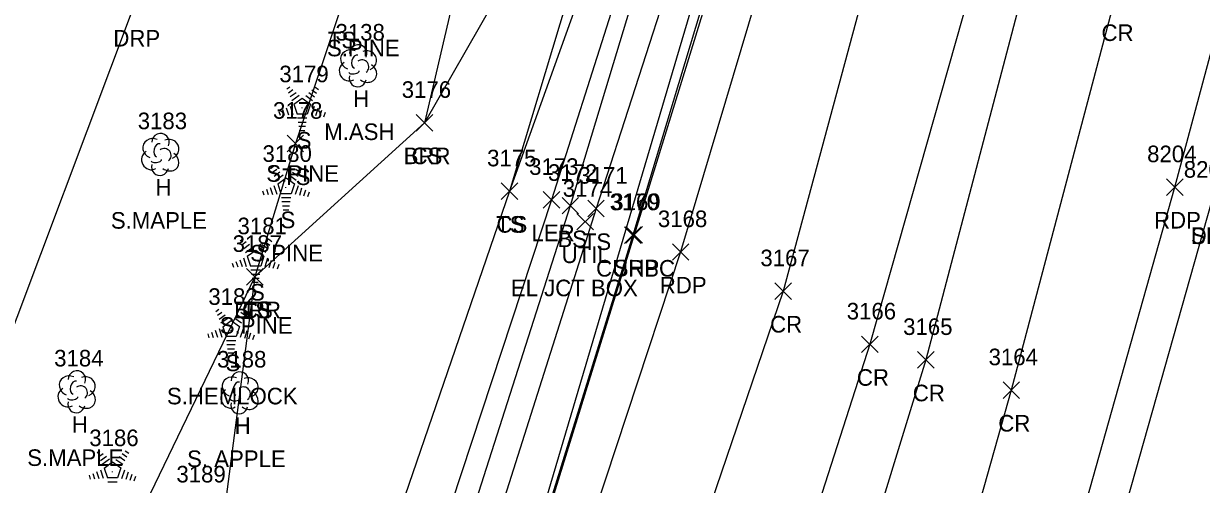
# Model space of a CAD drawing. Extents: x 1462089 to 1464015, y 730534 to 736144.
# Drawn here: x 1462997.1 to 1463139, y 733027.8 to 733083.4 of the extents above; entities that cross this region are included whole.
import ezdxf

# ---------------------------------------------------------------- set-up
doc = ezdxf.new("R2010")
doc.units = 0
for name, color, linetype in [('DCP', 7, 'Continuous'), ('L_A', 7, 'Continuous'), ('L_C', 7, 'Continuous'), ('L_I', 7, 'Continuous'), ('L_TIC', 7, 'Continuous'), ('LABL', 7, 'Continuous'), ('LARO', 7, 'Continuous'), ('LELB', 7, 'Continuous'), ('LTC', 7, 'Continuous'), ('LTD', 7, 'Continuous'), ('P_A', 7, 'Continuous'), ('P_I', 7, 'Continuous'), ('P_TIC', 7, 'Continuous'), ('PET', 7, 'Continuous'), ('PRC', 7, 'Continuous'), ('PSP', 7, 'Continuous'), ('R_A', 7, 'Continuous'), ('R_I', 7, 'Continuous'), ('R_TIC', 7, 'Continuous'), ('RC', 7, 'Continuous'), ('RDP', 7, 'Continuous'), ('U_A', 7, 'Continuous'), ('U_C', 7, 'Continuous'), ('U_I', 7, 'Continuous'), ('UDEFAULT', 7, 'Continuous')]:
    doc.layers.add(name, color=color, linetype=linetype)

msp = doc.modelspace()

# ---------------------------------------------------------------- linework, layer by layer
at = {"layer": 'DCP'}
msp.add_lwpolyline([(1463113.91, 733208.21), (1463020.77, 732893.28)], dxfattribs=at)
at = {"layer": 'L_TIC'}
for points in [[(1463044.39, 733070.47), (1463046.39, 733072.47)], [(1463046.39, 733070.47), (1463044.39, 733072.47)], [(1463044.39, 733070.47), (1463046.39, 733072.47)], [(1463046.39, 733070.47), (1463044.39, 733072.47)], [(1463028.83, 733067.95), (1463030.83, 733069.95)], [(1463030.83, 733067.95), (1463028.83, 733069.95)], [(1463054.63, 733062.21), (1463056.63, 733064.21)], [(1463056.63, 733062.21), (1463054.63, 733064.21)], [(1463054.63, 733062.21), (1463056.63, 733064.21)], [(1463056.63, 733062.21), (1463054.63, 733064.21)], [(1463059.71, 733061.18), (1463061.71, 733063.18)], [(1463061.71, 733061.18), (1463059.71, 733063.18)], [(1463061.97, 733060.46), (1463063.97, 733062.46)], [(1463063.97, 733060.46), (1463061.97, 733062.46)], [(1463065.07, 733060.12), (1463067.07, 733062.12)], [(1463067.07, 733060.12), (1463065.07, 733062.12)], [(1463023.96, 733051.89), (1463025.96, 733053.89)], [(1463025.96, 733051.89), (1463023.96, 733053.89)], [(1463023.96, 733051.89), (1463025.96, 733053.89)], [(1463025.96, 733051.89), (1463023.96, 733053.89)], [(1463023.96, 733051.89), (1463025.96, 733053.89)], [(1463025.96, 733051.89), (1463023.96, 733053.89)]]:
    msp.add_lwpolyline(points, dxfattribs=at)
at = {"layer": 'LABL'}
msp.add_lwpolyline([(1463052.45, 733194.5), (1463067.07, 733192.93), (1463078.58, 733189.91), (1463086.91, 733186.3), (1463094.26, 733183.58), (1463092.11, 733172.76), (1463083.33, 733140.42), (1463080.34, 733131.51), (1463076.28, 733126.39), (1463067.39, 733109.86), (1463045.39, 733071.47), (1463024.96, 733052.89)], dxfattribs=at)
at = {"layer": 'LARO'}
msp.add_lwpolyline([(1463094.76, 733228.15), (1463096.03, 733229.51), (1463107.11, 733225.67), (1463106.44, 733220.79), (1463101.84, 733210.57), (1463094.26, 733183.58), (1463093.23, 733172.66), (1463084.96, 733140.71), (1463082.5, 733130.85), (1463075.1, 733107.4), (1463060.71, 733062.18), (1463041.43, 733003.63), (1463027.29, 732956.25), (1463020.7, 732939.68), (1463009.72, 732922.59), (1463000.8, 732913.83)], dxfattribs=at)
at = {"layer": 'LELB'}
for points in [[(1463067.07, 733192.93), (1463070.43, 733198.24), (1463078.66, 733227.75), (1463094.76, 733228.15), (1463099.99, 733222.4), (1463095.74, 733212.27), (1463086.91, 733186.3), (1463084.26, 733175.21), (1463078.19, 733140.32), (1463061.26, 733133.55), (1463056.17, 733129.91), (1463054.78, 733128.23), (1463056, 733122.82), (1463058.28, 733122.51), (1463065.52, 733123.03), (1463076.28, 733126.39), (1463069.53, 733109.4), (1463055.63, 733063.21), (1463034.63, 733001.95)], [(1463108.71, 733226.1), (1463108.78, 733215.45), (1463107.91, 733210.67), (1463106.52, 733207.37), (1463097.65, 733182.34), (1463096.33, 733171.82), (1463062.97, 733061.46), (1463044.31, 733003.12), (1463029.33, 732955.28), (1463018.11, 732921.02), (1463012.52, 732895.45), (1463002.14, 732868.56), (1462989.94, 732828.37), (1462974.14, 732778.17), (1462962.05, 732738.86), (1462942.09, 732684.7)], [(1463108.71, 733226.1), (1463110.44, 733215.45), (1463109.61, 733208.14), (1463106.26, 733200.46), (1463099.08, 733171.5), (1463080.2, 733104.81), (1463066.07, 733061.12), (1463047.44, 733002.3), (1463031.89, 732954.26), (1463021.29, 732920.45), (1463016.04, 732893.81), (1463006.16, 732867.27), (1462993.39, 732826.96), (1462975.9, 732776.47), (1462964.59, 732738.3), (1462945.3, 732683.44)], [(1463084.96, 733140.71), (1463083.33, 733140.42), (1463075.18, 733134.32), (1463064.14, 733130.76), (1463056.73, 733129.29), (1463058.13, 733125.1), (1463066.3, 733126.91), (1463074.64, 733128.86), (1463080.34, 733131.51), (1463082.5, 733130.85), (1463071.67, 733107.97), (1463055.63, 733063.21)], [(1463058.13, 733125.1), (1463058.28, 733122.51), (1463056.05, 733119.51), (1463052.64, 733102.51), (1463045.39, 733071.47)], [(1463035.34, 733085.44), (1463029.83, 733068.95), (1463024.96, 733052.89), (1463005.74, 733013.02), (1462985.96, 732964.97), (1462972.93, 732929.05)], [(1463024.96, 733052.89), (1463019.37, 733009.96), (1463000.01, 732962.33), (1462984.86, 732926.01), (1462972.76, 732908.94), (1462960.37, 732884.47), (1462958.09, 732841.86), (1462948.33, 732829.18), (1462951.8, 732798.65), (1462940.09, 732777.68), (1462936.2, 732747.89), (1462927.88, 732723.49), (1462921.5, 732707.29), (1462904.86, 732665.94), (1462895.56, 732628.88), (1462895.22, 732616.02)]]:
    msp.add_lwpolyline(points, dxfattribs=at)
at = {"layer": 'LTC'}
for p, q in [((1463028.8, 733075.55), (1463029.15, 733075.81)), ((1463029.01, 733075.09), (1463029.53, 733075.47)), ((1463029.21, 733074.62), (1463029.92, 733075.13)), ((1463029.42, 733074.16), (1463030.3, 733074.79)), ((1463031.08, 733074.75), (1463031.89, 733074.16)), ((1463031.45, 733075.1), (1463032.13, 733074.6)), ((1463031.82, 733075.45), (1463032.37, 733075.05)), ((1463032.19, 733075.79), (1463032.61, 733075.49)), ((1463028.28, 733073.05), (1463028.5, 733072.4)), ((1463028.74, 733073.27), (1463029.01, 733072.43)), ((1463029.19, 733073.48), (1463029.53, 733072.46)), ((1463029.65, 733073.7), (1463030.66, 733074.44)), ((1463029.65, 733073.7), (1463030.04, 733072.51)), ((1463030.66, 733074.44), (1463031.66, 733073.71)), ((1463031.66, 733073.71), (1463031.27, 733072.51)), ((1463032.1, 733073.44), (1463031.76, 733072.4)), ((1463032.54, 733073.19), (1463032.25, 733072.31)), ((1463027.83, 733072.83), (1463027.98, 733072.37)), ((1463031.27, 733072.51), (1463030.04, 733072.51)), ((1463031.23, 733072.01), (1463030.08, 733072.01)), ((1463032.98, 733072.94), (1463032.75, 733072.21)), ((1463033.43, 733072.69), (1463033.24, 733072.12)), ((1463031.14, 733071.51), (1463030.16, 733071.51)), ((1463031.06, 733071.01), (1463030.23, 733071.01)), ((1463030.98, 733070.51), (1463030.3, 733070.51)), ((1463026.85, 733065.96), (1463027.2, 733066.21)), ((1463030.25, 733066.2), (1463030.67, 733065.89)), ((1463027.06, 733065.49), (1463027.59, 733065.88)), ((1463027.27, 733065.03), (1463027.97, 733065.54)), ((1463027.48, 733064.56), (1463028.36, 733065.2)), ((1463027.7, 733064.11), (1463028.71, 733064.84)), ((1463028.71, 733064.84), (1463029.71, 733064.11)), ((1463029.13, 733065.15), (1463029.94, 733064.56)), ((1463029.5, 733065.5), (1463030.18, 733065.01)), ((1463029.88, 733065.85), (1463030.43, 733065.45)), ((1463025.88, 733063.24), (1463026.03, 733062.77)), ((1463026.34, 733063.45), (1463026.55, 733062.8)), ((1463026.79, 733063.67), (1463027.06, 733062.83)), ((1463027.25, 733063.89), (1463027.58, 733062.87)), ((1463027.7, 733064.11), (1463028.09, 733062.91)), ((1463029.71, 733064.11), (1463029.32, 733062.91)), ((1463030.15, 733063.84), (1463029.81, 733062.8)), ((1463030.59, 733063.59), (1463030.31, 733062.71)), ((1463031.04, 733063.34), (1463030.8, 733062.61)), ((1463031.48, 733063.09), (1463031.29, 733062.52)), ((1463029.32, 733062.91), (1463028.09, 733062.91)), ((1463029.28, 733062.41), (1463028.14, 733062.41)), ((1463029.2, 733061.91), (1463028.21, 733061.91)), ((1463029.11, 733061.41), (1463028.28, 733061.41)), ((1463029.03, 733060.91), (1463028.35, 733060.91)), ((1463023.18, 733057.23), (1463023.54, 733057.49)), ((1463026.58, 733057.47), (1463027, 733057.16)), ((1463023.39, 733056.76), (1463023.92, 733057.15)), ((1463023.6, 733056.3), (1463024.31, 733056.81)), ((1463023.81, 733055.83), (1463024.69, 733056.47)), ((1463024.04, 733055.38), (1463025.05, 733056.11)), ((1463025.05, 733056.11), (1463026.04, 733055.39)), ((1463025.47, 733056.42), (1463026.28, 733055.84)), ((1463025.84, 733056.77), (1463026.52, 733056.28)), ((1463026.21, 733057.12), (1463026.76, 733056.72)), ((1463022.67, 733054.72), (1463022.88, 733054.07)), ((1463023.13, 733054.94), (1463023.4, 733054.11)), ((1463023.58, 733055.16), (1463023.91, 733054.14)), ((1463024.04, 733055.38), (1463024.42, 733054.18)), ((1463026.04, 733055.39), (1463025.65, 733054.18)), ((1463026.48, 733055.12), (1463026.14, 733054.08)), ((1463026.93, 733054.86), (1463026.64, 733053.98)), ((1463027.37, 733054.61), (1463027.13, 733053.89)), ((1463022.22, 733054.51), (1463022.37, 733054.04)), ((1463025.65, 733054.18), (1463024.42, 733054.18)), ((1463025.62, 733053.68), (1463024.47, 733053.68)), ((1463025.53, 733053.18), (1463024.54, 733053.18)), ((1463027.82, 733054.36), (1463027.63, 733053.79)), ((1463025.45, 733052.68), (1463024.62, 733052.68)), ((1463025.36, 733052.18), (1463024.69, 733052.18)), ((1463020.23, 733048.71), (1463020.59, 733048.97)), ((1463023.63, 733048.95), (1463024.05, 733048.65)), ((1463020.44, 733048.25), (1463020.97, 733048.63)), ((1463020.65, 733047.78), (1463021.35, 733048.29)), ((1463020.86, 733047.32), (1463021.74, 733047.95)), ((1463021.08, 733046.86), (1463022.1, 733047.6)), ((1463022.1, 733047.6), (1463023.09, 733046.87)), ((1463022.52, 733047.91), (1463023.33, 733047.32)), ((1463022.89, 733048.26), (1463023.57, 733047.76)), ((1463023.26, 733048.61), (1463023.81, 733048.21)), ((1463019.72, 733046.21), (1463019.93, 733045.56)), ((1463020.17, 733046.43), (1463020.45, 733045.59)), ((1463020.63, 733046.64), (1463020.96, 733045.62)), ((1463021.08, 733046.86), (1463021.47, 733045.67)), ((1463023.09, 733046.87), (1463022.7, 733045.67)), ((1463023.53, 733046.6), (1463023.19, 733045.56)), ((1463023.97, 733046.35), (1463023.69, 733045.46)), ((1463024.42, 733046.1), (1463024.18, 733045.37)), ((1463019.26, 733045.99), (1463019.42, 733045.52)), ((1463022.7, 733045.67), (1463021.47, 733045.67)), ((1463022.66, 733045.17), (1463021.52, 733045.17)), ((1463022.58, 733044.67), (1463021.59, 733044.67)), ((1463024.86, 733045.85), (1463024.68, 733045.27)), ((1463022.5, 733044.17), (1463021.66, 733044.17)), ((1463022.41, 733043.67), (1463021.74, 733043.67)), ((1463005.93, 733031.67), (1463006.28, 733031.93)), ((1463009.33, 733031.91), (1463009.75, 733031.6)), ((1463006.14, 733031.2), (1463006.67, 733031.59)), ((1463006.35, 733030.74), (1463007.05, 733031.25)), ((1463006.56, 733030.27), (1463007.44, 733030.91)), ((1463006.78, 733029.82), (1463007.79, 733030.55)), ((1463007.79, 733030.55), (1463008.79, 733029.83)), ((1463008.21, 733030.86), (1463009.02, 733030.28)), ((1463008.58, 733031.21), (1463009.26, 733030.72)), ((1463008.96, 733031.56), (1463009.51, 733031.16)), ((1463005.42, 733029.16), (1463005.63, 733028.51)), ((1463005.87, 733029.38), (1463006.14, 733028.55)), ((1463006.33, 733029.6), (1463006.66, 733028.58)), ((1463006.78, 733029.82), (1463007.17, 733028.62)), ((1463008.79, 733029.83), (1463008.4, 733028.62)), ((1463009.23, 733029.56), (1463008.89, 733028.52)), ((1463009.67, 733029.3), (1463009.39, 733028.42)), ((1463010.12, 733029.05), (1463009.88, 733028.33)), ((1463004.96, 733028.95), (1463005.11, 733028.48)), ((1463008.4, 733028.62), (1463007.17, 733028.62)), ((1463008.36, 733028.12), (1463007.22, 733028.12)), ((1463010.56, 733028.8), (1463010.37, 733028.23))]:
    msp.add_line(p, q, dxfattribs=at)
at = {"layer": 'LTD'}
for p, q in [((1463037.36, 733078.38), (1463037.36, 733078.38)), ((1463037.36, 733078.38), (1463037.36, 733078.38)), ((1463013.52, 733067.69), (1463013.52, 733067.69)), ((1463013.52, 733067.69), (1463013.52, 733067.69)), ((1463003.45, 733039.07), (1463003.45, 733039.07)), ((1463003.45, 733039.07), (1463003.45, 733039.07)), ((1463023.08, 733038.94), (1463023.08, 733038.94)), ((1463023.08, 733038.94), (1463023.08, 733038.94))]:
    msp.add_line(p, q, dxfattribs=at)
for centre in [(1463037.41, 733079.82), (1463013.57, 733069.13), (1463003.5, 733040.5), (1463023.13, 733040.37)]:
    msp.add_arc(centre, 1.05, 335.5272, 180.9563, dxfattribs=at)
for centre, major_axis, ratio, start_param, end_param in [((1463036.57, 733079.05), (1.21, -0.51), 0.895232, 1.570796, 4.712389), ((1463038.4, 733078.97), (-1.14, -0.48), 0.949671, 1.570796, 4.712389), ((1463036.28, 733077.68), (0.58, -1.04), 0.959034, 3.141593, 6.283185), ((1463037.15, 733078.84), (-0.208, -0.792), 0.645439, 3.141593, 6.283185), ((1463037.86, 733078.22), (-0.5, 0.667), 0.989748, 3.141593, 6.283185), ((1463036.9, 733077.63), (-0.625, -0.083), 0.423636, 0, 3.141593), ((1463038.36, 733077.55), (-1.09, 0.79), 0.841452, 1.570796, 4.712389), ((1463037.36, 733076.88), (0.26, 1.06), 0.942809, 1.570796, 4.712389), ((1463012.73, 733068.36), (1.21, -0.51), 0.895232, 1.570796, 4.712389), ((1463013.32, 733068.15), (-0.208, -0.792), 0.645439, 3.141593, 6.283185), ((1463014.57, 733068.28), (-1.14, -0.48), 0.949671, 1.570796, 4.712389), ((1463012.44, 733066.98), (0.58, -1.04), 0.959034, 3.141593, 6.283185), ((1463014.02, 733067.53), (-0.5, 0.667), 0.989748, 3.141593, 6.283185), ((1463014.52, 733066.86), (-1.09, 0.79), 0.841452, 1.570796, 4.712389), ((1463013.52, 733066.19), (0.26, 1.06), 0.942809, 1.570796, 4.712389), ((1463013.07, 733066.94), (-0.625, -0.083), 0.423636, 0, 3.141593), ((1463002.66, 733039.73), (1.21, -0.51), 0.895232, 1.570796, 4.712389), ((1463003.24, 733039.52), (-0.208, -0.792), 0.645439, 3.141593, 6.283185), ((1463004.49, 733039.65), (-1.14, -0.48), 0.949671, 1.570796, 4.712389), ((1463022.29, 733039.6), (1.21, -0.51), 0.895232, 1.570796, 4.712389), ((1463024.12, 733039.52), (-1.14, -0.48), 0.949671, 1.570796, 4.712389), ((1463002.37, 733038.36), (0.58, -1.04), 0.959034, 3.141593, 6.283185), ((1463003.95, 733038.9), (-0.5, 0.667), 0.989748, 3.141593, 6.283185), ((1463004.45, 733038.23), (-1.09, 0.79), 0.841452, 1.570796, 4.712389), ((1463022, 733038.23), (0.58, -1.04), 0.959034, 3.141593, 6.283185), ((1463022.87, 733039.4), (-0.208, -0.792), 0.645439, 3.141593, 6.283185), ((1463023.58, 733038.77), (-0.5, 0.667), 0.989748, 3.141593, 6.283185), ((1463024.08, 733038.1), (-1.09, 0.79), 0.841452, 1.570796, 4.712389), ((1463003.45, 733037.57), (0.26, 1.06), 0.942809, 1.570796, 4.712389), ((1463002.99, 733038.32), (-0.625, -0.083), 0.423636, 0, 3.141593), ((1463023.08, 733037.44), (0.26, 1.06), 0.942809, 1.570796, 4.712389), ((1463022.62, 733038.19), (-0.625, -0.083), 0.423636, 0, 3.141593)]:
    msp.add_ellipse(centre, major_axis=major_axis, ratio=ratio, start_param=start_param, end_param=end_param, dxfattribs=at)
at = {"layer": 'P_TIC'}
for points in [[(1463134.84, 733062.71), (1463136.84, 733064.71)], [(1463136.84, 733062.71), (1463134.84, 733064.71)], [(1463069.66, 733056.94), (1463071.66, 733058.94)], [(1463071.66, 733056.94), (1463069.66, 733058.94)], [(1463075.27, 733054.88), (1463077.27, 733056.88)], [(1463077.27, 733054.88), (1463075.27, 733056.88)], [(1463087.62, 733050.16), (1463089.62, 733052.16)], [(1463089.62, 733050.16), (1463087.62, 733052.16)], [(1463098.08, 733043.74), (1463100.08, 733045.74)], [(1463100.08, 733043.74), (1463098.08, 733045.74)], [(1463104.83, 733041.87), (1463106.83, 733043.87)], [(1463106.83, 733041.87), (1463104.83, 733043.87)], [(1463115.13, 733038.22), (1463117.13, 733040.22)], [(1463117.13, 733038.22), (1463115.13, 733040.22)]]:
    msp.add_lwpolyline(points, dxfattribs=at)
at = {"layer": 'PET'}
for points in [[(1463023.48, 732671), (1463036.19, 732713.31), (1463039.97, 732724.95), (1463046.42, 732748.22), (1463045.94, 732761.16), (1463059.87, 732803.81), (1463070.46, 732836.88), (1463084.18, 732884.08), (1463100.27, 732939.23), (1463111.27, 732977.09), (1463121.46, 733012.56), (1463135.84, 733063.71), (1463147.86, 733108.52), (1463159.44, 733157.54), (1463168.48, 733199.6), (1463175.72, 733236.25), (1463184.37, 733283.25), (1463191.27, 733323.49), (1463191.08, 733323.84), (1463204.04, 733400.9), (1463213.28, 733462.86)], [(1463162.64, 733438.25), (1463155.29, 733389.19), (1463147.91, 733342.63), (1463141.51, 733306.47), (1463132.06, 733260.3), (1463123.36, 733223.56), (1463108.71, 733168.54), (1463089.87, 733101.56), (1463076.27, 733055.88), (1463056.85, 732997.04), (1463043.72, 732952), (1463030.35, 732910.94), (1463015.8, 732864.49), (1463002.53, 732823.32), (1462986.53, 732773.32), (1462974.36, 732735), (1462957.21, 732680.82)]]:
    msp.add_lwpolyline(points, dxfattribs=at)
at = {"layer": 'PRC'}
for points in [[(1463173.05, 733431.97), (1463166.54, 733387.93), (1463158.95, 733340.73), (1463152.26, 733304.55), (1463143.59, 733257.28), (1463135.29, 733220.7), (1463120.9, 733164.91), (1463101.36, 733098.43), (1463088.62, 733051.16), (1463070, 732996.41), (1463055.29, 732948.06), (1463043.07, 732909.01), (1463027.36, 732860.42), (1463013.91, 732819.27), (1462999.18, 732769.26), (1462985.72, 732731.93), (1462969.44, 732677.27)], [(1463184.26, 733428.99), (1463177.5, 733386.21), (1463169.42, 733335), (1463162.87, 733301.13), (1463154.54, 733254.52), (1463145.29, 733216.48), (1463131.67, 733162.65), (1463112.82, 733093.24), (1463099.08, 733044.74), (1463082.5, 732993.09), (1463066.93, 732944.79), (1463054.22, 732905.14), (1463038.5, 732856.13), (1463025.08, 732814.55), (1463009.9, 732766.25), (1462997.49, 732727.73), (1462980.34, 732670.55), (1462968.82, 732637.25), (1462956.14, 732592.49), (1462943.23, 732555.63), (1462933.85, 732526.13), (1462921.41, 732485.16), (1462905.69, 732440.94), (1462895.98, 732404.53)], [(1463173.56, 733299.02), (1463165.51, 733252.57), (1463157.36, 733210.85), (1463147.48, 733159.84), (1463128.56, 733086.33), (1463116.13, 733039.22), (1463100.45, 732983.58), (1463087.95, 732938.84), (1463073.8, 732896.76), (1463059.6, 732849.78), (1463047.56, 732806.21), (1463032.36, 732758.17), (1463016.83, 732714.7), (1463001.87, 732663.36), (1462991.08, 732629.32), (1462977.35, 732584.7), (1462966.06, 732548.54), (1462956.48, 732518.6), (1462941.54, 732474.04), (1462928.1, 732429.75), (1462916.12, 732396.98)], [(1463154.54, 733254.52), (1463146.61, 733215.85), (1463135.44, 733161.47), (1463118.39, 733090.76), (1463105.83, 733042.87), (1463089.37, 732989.24), (1463076.43, 732943.44), (1463063.88, 732901.54), (1463049.78, 732852.76), (1463036.58, 732810.58), (1463021.66, 732763.56), (1463007.35, 732718.7), (1462991.11, 732667.44), (1462980.42, 732633.72), (1462966.43, 732588.15), (1462955.05, 732551.99), (1462945.51, 732521.94), (1462931.54, 732478.17), (1462917.14, 732435.42), (1462906.01, 732400.46)]]:
    msp.add_lwpolyline(points, dxfattribs=at)
at = {"layer": 'PSP'}
for points in [[(1463046.42, 732748.22), (1463053.17, 732770.64), (1463063.86, 732801.92), (1463074.6, 732835.37), (1463088.19, 732883.02), (1463104.54, 732937.8), (1463115.69, 732976.25), (1463126.02, 733011.46), (1463140.26, 733061.84), (1463152.14, 733107.42), (1463163.97, 733156.32), (1463173.72, 733198.02), (1463181.46, 733234.06), (1463190.45, 733280.83), (1463197.61, 733321.61), (1463206.08, 733372.72), (1463210.25, 733399.69), (1463219.8, 733463.02)], [(1463155.47, 733437.1), (1463151.69, 733409.08), (1463149, 733391.93), (1463141.96, 733349.08), (1463135.18, 733308.49), (1463125.93, 733264.09), (1463122.72, 733251.49), (1463119.11, 733234.45), (1463113.24, 733211.25), (1463103.08, 733170.52), (1463084.78, 733103.69), (1463070.66, 733057.94), (1463052.86, 733000.45), (1463038.28, 732952.98), (1463025.31, 732912.14), (1463010.74, 732866.35), (1462997.43, 732825.46), (1462981.2, 732774.91), (1462968.73, 732736.5), (1462951.61, 732681.88)]]:
    msp.add_lwpolyline(points, dxfattribs=at)
at = {"layer": 'R_TIC'}
for points in [[(1463069.5, 733056.91), (1463071.5, 733058.91)], [(1463071.5, 733056.91), (1463069.5, 733058.91)]]:
    msp.add_lwpolyline(points, dxfattribs=at)
at = {"layer": 'RC'}
msp.add_lwpolyline([(1463111.2, 733221.62), (1463111.65, 733221.54), (1463112.56, 733218.83), (1463113.16, 733213.96), (1463112.93, 733211.4), (1463102.86, 733170.54), (1463084.32, 733103.79), (1463070.5, 733057.91), (1463052.69, 733000.48), (1463038.08, 732953.17), (1463025.2, 732912.25), (1463010.5, 732866.43), (1462997.21, 732825.5), (1462981.06, 732775.17), (1462968.5, 732736.53), (1462951.35, 732681.84)], dxfattribs=at)
at = {"layer": 'RDP'}
msp.add_lwpolyline([(1463003.46, 733112.43), (1463010.21, 733105.22), (1463012.77, 733098.29), (1463010.4, 733085.66), (1462993.36, 733040.36), (1462985.36, 733018.62), (1462967.62, 732969.66)], dxfattribs=at)
at = {"layer": 'UDEFAULT'}
for points in [[(1463063.76, 733058.54), (1463065.76, 733060.54)], [(1463065.76, 733058.54), (1463063.76, 733060.54)]]:
    msp.add_lwpolyline(points, dxfattribs=at)

# ---------------------------------------------------------------- texts
at = {"layer": 'L_A'}
for s, p in [('TS', (1463033.75, 733080.44)), ('H', (1463036.79, 733073.38)), ('S', (1463029.99, 733068.35)), ('BRR', (1463042.88, 733066.47)), ('CS', (1463043.83, 733066.47)), ('TS', (1463028.24, 733063.95)), ('H', (1463012.96, 733062.69)), ('S', (1463028.04, 733058.75)), ('TS', (1463054.04, 733058.21)), ('CS', (1463054.07, 733058.21)), ('LER', (1463058.29, 733057.18)), ('BS', (1463061.41, 733056.46)), ('TS', (1463064.48, 733056.12)), ('S', (1463024.37, 733050.02)), ('BRR', (1463022.45, 733047.89)), ('TS', (1463023.37, 733047.89)), ('CS', (1463023.4, 733047.89)), ('S', (1463021.42, 733041.5)), ('H', (1463002.88, 733034.07)), ('H', (1463022.51, 733033.94))]:
    msp.add_text(s, height=2, dxfattribs=at).set_placement(p)
at = {"layer": 'L_C'}
for s, p in [('S.PINE', (1463033.64, 733079.48)), ('M.ASH', (1463033.31, 733069.38)), ('S.PINE', (1463026.33, 733064.35)), ('S.MAPLE', (1463007.59, 733058.69)), ('S.PINE', (1463024.39, 733054.75)), ('S.PINE', (1463020.72, 733046.02)), ('S.HEMLOCK', (1463014.35, 733037.5)), ('S.MAPLE', (1462997.51, 733030.07)), ('S. APPLE', (1463016.78, 733029.94))]:
    msp.add_text(s, height=2, dxfattribs=at).set_placement(p)
at = {"layer": 'L_I'}
for s, p in [('3138', (1463034.67, 733081.38)), ('3179', (1463027.9, 733076.35)), ('3176', (1463042.65, 733074.47)), ('3176', (1463042.65, 733074.47)), ('3178', (1463027.14, 733071.95)), ('3183', (1463010.83, 733070.69)), ('3180', (1463025.87, 733066.75)), ('3175', (1463052.94, 733066.21)), ('3175', (1463052.94, 733066.21)), ('3173', (1463058.01, 733065.18)), ('3172', (1463060.28, 733064.46)), ('3171', (1463063.94, 733064.12)), ('3181', (1463022.86, 733058.02)), ('3187', (1463022.27, 733055.89)), ('3187', (1463022.27, 733055.89)), ('3187', (1463022.27, 733055.89)), ('3182', (1463019.34, 733049.5)), ('3184', (1463000.76, 733042.07)), ('3188', (1463020.39, 733041.94)), ('3186', (1463004.99, 733032.46)), ('3189', (1463015.49, 733028.08))]:
    msp.add_text(s, height=2, dxfattribs=at).set_placement(p)
at = {"layer": 'LTC'}
for p in [(1463030.54, 733073.45), (1463028.6, 733063.85), (1463024.93, 733055.12), (1463021.98, 733046.61), (1463007.68, 733029.56)]:
    msp.add_text('.', height=1.04, rotation=270, dxfattribs=at).set_placement(p)
at = {"layer": 'P_A'}
for s, p in [('CR', (1463127, 733081.33)), ('RDP', (1463133.33, 733058.71)), ('SHP', (1463137.79, 733056.84)), ('SHP', (1463068.2, 733052.94)), ('RDP', (1463073.76, 733050.88)), ('CR', (1463087.05, 733046.16)), ('CR', (1463097.52, 733039.74)), ('CR', (1463104.26, 733037.87)), ('CR', (1463114.56, 733034.22))]:
    msp.add_text(s, height=2, dxfattribs=at).set_placement(p)
at = {"layer": 'P_I'}
for s, p in [('8204', (1463132.5, 733066.71)), ('8203', (1463136.92, 733064.84)), ('3169', (1463067.91, 733060.94)), ('3168', (1463073.53, 733058.88)), ('3167', (1463085.88, 733054.16)), ('3166', (1463096.29, 733047.74)), ('3165', (1463103.09, 733045.87)), ('3164', (1463113.39, 733042.22))]:
    msp.add_text(s, height=2, dxfattribs=at).set_placement(p)
at = {"layer": 'R_A'}
for s, p in [('DRP', (1463007.89, 733080.66)), ('DRP', (1463137.75, 733056.84)), ('CURBC', (1463066.08, 733052.91))]:
    msp.add_text(s, height=2, dxfattribs=at).set_placement(p)
at = {"layer": 'R_I'}
for s, p in [('8203', (1463136.92, 733064.84)), ('3170', (1463067.72, 733060.91))]:
    msp.add_text(s, height=2, dxfattribs=at).set_placement(p)
at = {"layer": 'U_A'}
msp.add_text('UTIL', height=2, dxfattribs=at).set_placement((1463061.93, 733054.54))
at = {"layer": 'U_C'}
msp.add_text('EL JCT BOX', height=2, dxfattribs=at).set_placement((1463055.8, 733050.54))
at = {"layer": 'U_I'}
msp.add_text('3174', height=2, dxfattribs=at).set_placement((1463062.07, 733062.54))

doc.saveas('drawing.dxf')
